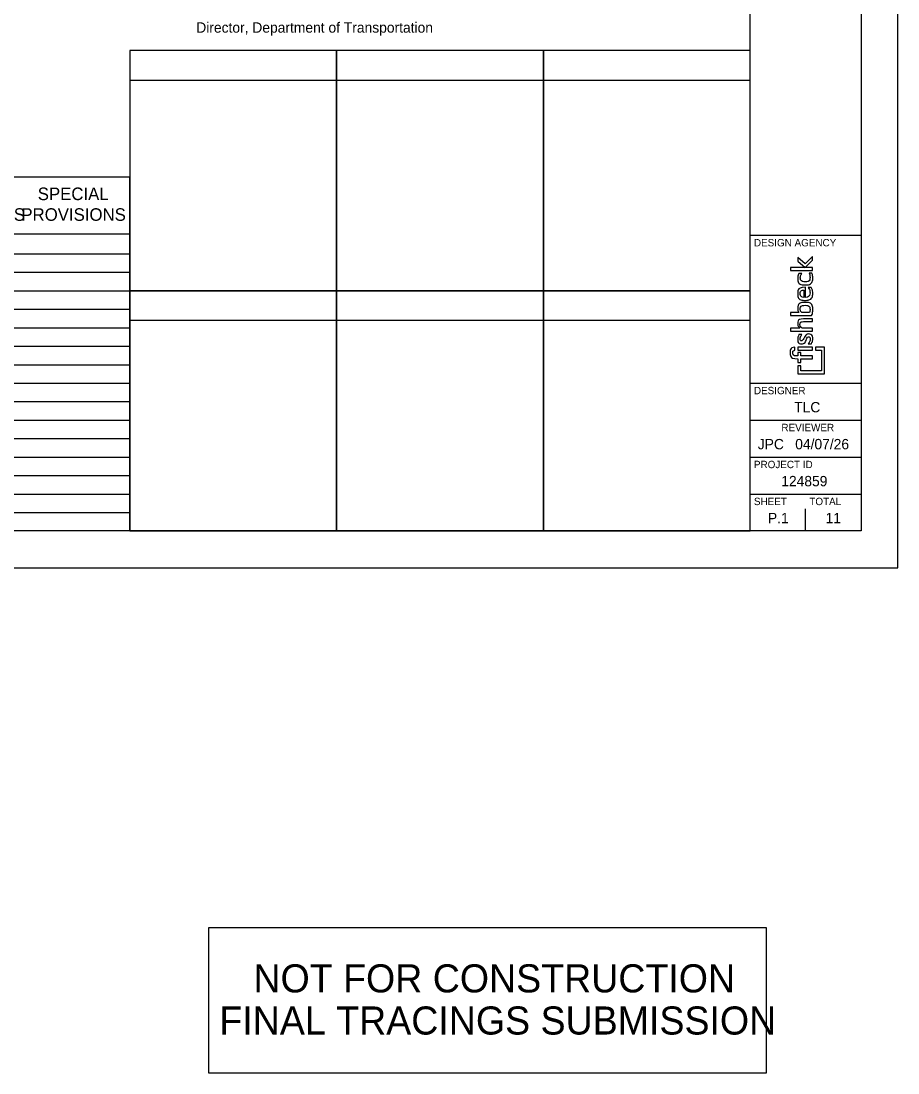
# Model space of a CAD drawing. Extents: x 0 to 34, y -6.8 to 22.
# Drawn here: x 22.13 to 34, y -6.83 to 7.4 of the extents above; entities that cross this region are included whole.
import ezdxf

# ---------------------------------------------------------------- set-up
doc = ezdxf.new("R2010")
doc.units = 0
for name, color, linetype in [('GM_X_County', 7, 'Continuous'), ('GM_X_County_Road_Text', 7, 'Continuous'), ('GM_X_Minor_Lake', 7, 'Continuous'), ('GM_X_Minor_Lake_Text', 7, 'Continuous'), ('GM_X_Minor_River_Text', 7, 'Continuous')]:
    doc.layers.add(name, color=color, linetype=linetype)

msp = doc.modelspace()

# ---------------------------------------------------------------- linework, layer by layer
at = {"layer": 'GM_X_County'}
msp.add_lwpolyline([(0, 0), (34, 0), (34, 22), (0, 22)], close=True, dxfattribs=at)
at = {"layer": 'GM_X_County_Road_Text'}
msp.add_lwpolyline([(32.222, -4.869), (24.666, -4.869), (24.666, -6.832), (32.222, -6.832)], close=True, dxfattribs=at)
at = {"layer": 'GM_X_Minor_Lake_Text'}
for p, q in [((23.6, 6.6), (26.4, 6.6)), ((26.4, 6.6), (29.2, 6.6)), ((29.2, 6.6), (32, 6.6)), ((10.15, 5.292), (23.6, 5.292)), ((23.6, 0.5), (23.6, 5.292)), ((10.15, 4.521), (23.6, 4.521)), ((10.15, 4.25), (23.6, 4.25)), ((32.646, 4.198), (32.646, 4.151)), ((32.742, 4.114), (32.646, 4.198)), ((32.646, 4.151), (32.742, 4.065)), ((32.842, 4.215), (32.742, 4.114)), ((32.742, 4.065), (32.842, 4.163)), ((32.842, 4.163), (32.842, 4.215)), ((10.15, 4), (23.6, 4)), ((32.544, 4.063), (32.544, 4.024)), ((32.842, 4.063), (32.544, 4.063)), ((32.544, 4.024), (32.842, 4.024)), ((32.835, 3.987), (32.796, 3.987)), ((32.842, 4.024), (32.842, 4.063)), ((32.697, 3.983), (32.656, 3.983)), ((10.15, 3.75), (23.6, 3.75)), ((32.724, 3.758), (32.724, 3.66)), ((32.75, 3.659), (32.75, 3.797)), ((32.823, 3.793), (32.785, 3.793)), ((10.15, 3.5), (23.6, 3.5)), ((32.803, 3.454), (32.697, 3.454)), ((32.75, 3.5), (32.75, 3.5)), ((23.6, 3.35), (26.4, 3.35)), ((26.4, 3.35), (29.2, 3.35)), ((29.2, 3.35), (32, 3.35)), ((10.15, 3.25), (23.6, 3.25)), ((32.697, 3.156), (32.658, 3.156)), ((10.15, 3), (23.6, 3)), ((32.786, 3.032), (32.828, 3.032)), ((32.603, 2.948), (32.603, 2.987)), ((32.646, 2.987), (32.646, 2.948)), ((32.842, 2.987), (32.646, 2.987)), ((32.646, 2.948), (32.842, 2.948)), ((32.842, 2.948), (32.842, 2.987)), ((33.005, 2.987), (32.885, 2.987)), ((32.885, 2.987), (32.885, 2.948)), ((32.885, 2.948), (32.966, 2.948)), ((32.966, 2.948), (32.966, 2.667)), ((33.005, 2.628), (33.005, 2.987)), ((10.15, 2.75), (23.6, 2.75)), ((32.685, 2.734), (32.646, 2.734)), ((32.646, 2.734), (32.646, 2.628)), ((32.685, 2.667), (32.685, 2.734)), ((32.646, 2.628), (33.005, 2.628)), ((32.966, 2.667), (32.685, 2.667)), ((10.15, 2.5), (23.6, 2.5)), ((10.15, 2.25), (23.6, 2.25)), ((10.15, 2), (23.6, 2)), ((10.15, 1.75), (23.6, 1.75)), ((10.15, 1.5), (23.6, 1.5)), ((10.15, 1.25), (23.6, 1.25)), ((10.15, 1), (23.6, 1)), ((10.15, 0.75), (23.6, 0.75)), ((32.75, 0.5), (32.75, 0.8)), ((32.375, 0.675), (32.375, 0.675))]:
    msp.add_line(p, q, dxfattribs=at)
for points in [[(26.4, 7), (23.6, 7), (23.6, 3.75), (26.4, 3.75)], [(29.2, 7), (26.4, 7), (26.4, 3.75), (29.2, 3.75)], [(32, 7), (29.2, 7), (29.2, 3.75), (32, 3.75)], [(26.4, 3.75), (23.6, 3.75), (23.6, 0.5), (26.4, 0.5)], [(29.2, 3.75), (26.4, 3.75), (26.4, 0.5), (29.2, 0.5)], [(32, 3.75), (29.2, 3.75), (29.2, 0.5), (32, 0.5)]]:
    msp.add_lwpolyline(points, close=True, dxfattribs=at)
for points in [[(32.66, 3.454), (32.544, 3.454), (32.544, 3.415), (32.831, 3.415)], [(32.721, 3.332), (32.842, 3.332), (32.842, 3.37), (32.722, 3.37)], [(32.672, 3.245), (32.672, 3.244), (32.544, 3.244), (32.544, 3.205), (32.842, 3.205), (32.842, 3.244), (32.701, 3.244)], [(32.646, 2.831), (32.646, 2.778), (32.685, 2.778), (32.685, 2.831), (32.842, 2.831), (32.842, 2.869), (32.685, 2.869), (32.685, 2.913), (32.646, 2.913), (32.646, 2.869)]]:
    msp.add_lwpolyline(points, dxfattribs=at)
for points in [[(32.656, 3.983), (32.647, 3.964), (32.642, 3.949), (32.642, 3.926), (32.642, 3.867), (32.683, 3.829), (32.748, 3.829), (32.805, 3.829), (32.846, 3.87), (32.846, 3.929), (32.846, 3.949), (32.841, 3.974), (32.835, 3.987)], [(32.796, 3.987), (32.805, 3.968), (32.809, 3.952), (32.809, 3.935), (32.809, 3.895), (32.785, 3.869), (32.744, 3.869), (32.705, 3.869), (32.678, 3.894), (32.678, 3.929), (32.678, 3.946), (32.682, 3.961), (32.697, 3.983)], [(32.75, 3.797), (32.677, 3.797), (32.642, 3.764), (32.642, 3.712), (32.642, 3.658), (32.682, 3.62), (32.742, 3.62), (32.796, 3.62), (32.846, 3.654), (32.846, 3.715), (32.846, 3.748), (32.839, 3.77), (32.823, 3.793)], [(32.724, 3.66), (32.693, 3.665), (32.676, 3.683), (32.676, 3.713), (32.676, 3.74), (32.695, 3.757), (32.724, 3.758)], [(32.785, 3.793), (32.8, 3.771), (32.809, 3.748), (32.809, 3.725), (32.809, 3.687), (32.789, 3.665), (32.75, 3.659)], [(32.831, 3.415), (32.84, 3.435), (32.846, 3.462), (32.846, 3.488), (32.846, 3.554), (32.806, 3.593), (32.74, 3.593), (32.684, 3.593), (32.642, 3.557), (32.642, 3.508), (32.642, 3.489), (32.648, 3.471), (32.66, 3.454)], [(32.697, 3.454), (32.682, 3.471), (32.677, 3.483), (32.677, 3.499), (32.677, 3.531), (32.704, 3.553), (32.746, 3.553), (32.783, 3.553), (32.809, 3.528), (32.809, 3.493), (32.809, 3.482), (32.807, 3.466), (32.803, 3.454)], [(32.722, 3.37), (32.668, 3.37), (32.642, 3.342), (32.642, 3.304), (32.642, 3.282), (32.653, 3.26), (32.672, 3.245)], [(32.701, 3.244), (32.681, 3.263), (32.673, 3.276), (32.673, 3.293), (32.673, 3.317), (32.692, 3.332), (32.721, 3.332)], [(32.658, 3.156), (32.647, 3.135), (32.642, 3.116), (32.642, 3.098), (32.642, 3.059), (32.662, 3.033), (32.695, 3.033), (32.748, 3.033), (32.763, 3.125), (32.79, 3.125), (32.804, 3.125), (32.811, 3.112), (32.812, 3.096), (32.812, 3.08), (32.804, 3.057), (32.786, 3.032)], [(32.828, 3.032), (32.841, 3.057), (32.846, 3.076), (32.846, 3.1), (32.846, 3.137), (32.823, 3.165), (32.788, 3.165), (32.768, 3.165), (32.755, 3.153), (32.733, 3.121), (32.713, 3.086), (32.703, 3.073), (32.694, 3.073), (32.684, 3.073), (32.676, 3.083), (32.676, 3.099), (32.676, 3.113), (32.682, 3.134), (32.697, 3.156)], [(32.603, 2.987), (32.565, 2.986), (32.54, 2.957), (32.54, 2.914), (32.54, 2.86), (32.574, 2.829), (32.646, 2.831)], [(32.646, 2.869), (32.598, 2.866), (32.575, 2.882), (32.575, 2.913), (32.575, 2.931), (32.584, 2.941), (32.603, 2.948)]]:
    msp.add_open_spline(points, degree=3, dxfattribs=at)
at = {"layer": 'GM_X_Minor_River_Text'}
for p, q in [((32, 0.5), (32, 21.5)), ((32, 4.5), (33.5, 4.5)), ((32, 2.5), (33.5, 2.5)), ((32, 2), (33.5, 2)), ((32, 1.5), (33.5, 1.5)), ((32, 1), (33.5, 1))]:
    msp.add_line(p, q, dxfattribs=at)
msp.add_lwpolyline([(1.5, 21.5), (33.5, 21.5), (33.5, 0.5), (1.5, 0.5)], close=True, dxfattribs=at)

# ---------------------------------------------------------------- texts
at = {"layer": 'GM_X_County_Road_Text'}
for s, p in [('NOT FOR CONSTRUCTION', (25.274, -5.742)), ('FINAL TRACINGS SUBMISSION', (24.813, -6.312))]:
    msp.add_text(s, height=0.38, dxfattribs=at).set_placement(p)
at = {"layer": 'GM_X_Minor_Lake'}
for s, height, p in [('Director, Department of Transportation', 0.14, (24.5, 7.241)), ('Director, Department of Transportation', 0.14, (24.5, 7.241)), ('SPECIAL', 0.17, (22.354, 4.976)), ('SPECIFICATIONS', 0.17, (20.287, 4.696)), ('PROVISIONS', 0.17, (22.132, 4.696))]:
    msp.add_text(s, height=height, dxfattribs=at).set_placement(p)
at = {"layer": 'GM_X_Minor_Lake_Text'}
for s, height, p in [('DESIGN AGENCY', 0.1, (32.05, 4.35)), ('DESIGNER', 0.1, (32.05, 2.35)), ('TLC', 0.14, (32.595, 2.105)), ('REVIEWER', 0.1, (32.422, 1.85)), ('JPC', 0.14, (32.102, 1.605)), ('04/07/26', 0.14, (32.609, 1.605)), ('PROJECT ID', 0.1, (32.05, 1.35)), ('124859', 0.14, (32.42, 1.105)), ('SHEET', 0.1, (32.05, 0.85)), ('TOTAL', 0.1, (32.8, 0.85)), ('P.1', 0.14, (32.24, 0.605)), ('11', 0.14, (33.019, 0.605))]:
    msp.add_text(s, height=height, dxfattribs=at).set_placement(p)

doc.saveas('drawing.dxf')
